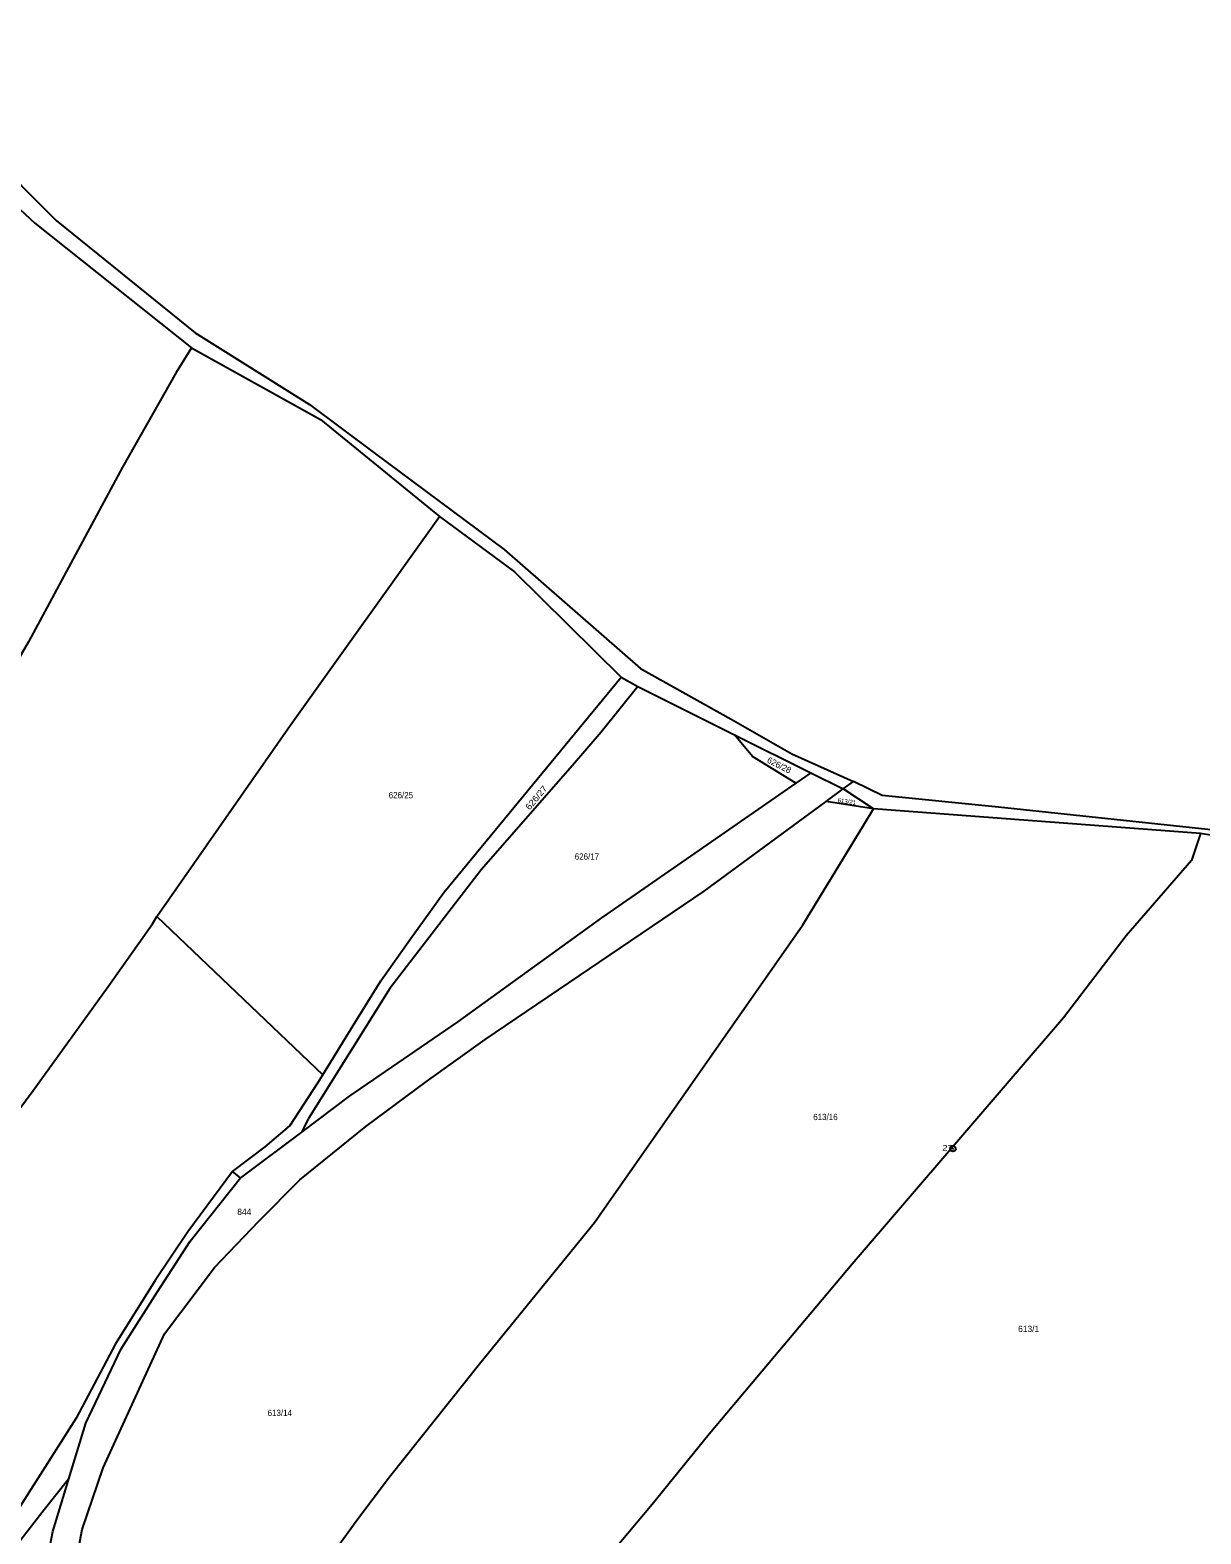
# Model space of a CAD drawing. Extents: x -687135 to -684370, y -1007309 to -1005782.
# Drawn here: x -684911.1 to -684594.1, y -1006317.9 to -1005910.8 of the extents above; entities that cross this region are included whole.
import ezdxf
from ezdxf.enums import TextEntityAlignment as Align

# ---------------------------------------------------------------- set-up
doc = ezdxf.new("R2010")
doc.units = 0
doc.header["$LTSCALE"] = 0.68
doc.layers.add('1', color=7, linetype='Continuous', lineweight=25)
doc.layers.add('8', color=7, linetype='Continuous', lineweight=25)
doc.layers.add('2', color=7, linetype='Continuous')

msp = doc.modelspace()

# ---------------------------------------------------------------- linework, layer by layer
at = {"layer": '1'}
for p, q in [((-684699.72, -1006111.87), (-684703.77, -1006114.68)), ((-684695.61, -1006119.67), (-684690.94, -1006116.24)), ((-684682.73, -1006121.59), (-684690.94, -1006116.24)), ((-684682.73, -1006121.59), (-684695.61, -1006119.67)), ((-684594.2, -1006128.33), (-684682.73, -1006121.59)), ((-684876.78, -1006150.79), (-684831.81, -1006193.68)), ((-684854.08, -1006221.54), (-684856.23, -1006219.78))]:
    msp.add_line(p, q, dxfattribs=at)
for points in [[(-684942.19, -1005910.78), (-684922.85, -1005943.49), (-684903.97, -1005962.38), (-684866.37, -1005992.78), (-684835.47, -1006012.17), (-684817.9, -1006025.25)], [(-684924.69, -1005949.22), (-684909.75, -1005963.09), (-684867.33, -1005996.85)], [(-684867.33, -1005996.85), (-684871.56, -1006003.53), (-684886.02, -1006029.12), (-684911.48, -1006076.41), (-684930.17, -1006108.46)], [(-684867.33, -1005996.85), (-684832.43, -1006016.17), (-684800.23, -1006042.43)], [(-684817.9, -1006025.25), (-684782.71, -1006051.45), (-684745.81, -1006083.61), (-684721.3, -1006097.36)], [(-684876.78, -1006150.79), (-684840.65, -1006099.06), (-684800.23, -1006042.43)], [(-684800.23, -1006042.43), (-684779.9, -1006057.47), (-684751.1, -1006085.93)], [(-684831.81, -1006193.68), (-684823.6, -1006180.27), (-684816.1, -1006168.18), (-684808.07, -1006156.86), (-684799.02, -1006144.25), (-684751.1, -1006085.93)], [(-684751.1, -1006085.93), (-684746.55, -1006088.53), (-684720.38, -1006101.58), (-684699.72, -1006111.87), (-684690.94, -1006116.24), (-684688.19, -1006114.23)], [(-684746.55, -1006088.53), (-684756.43, -1006100.82), (-684764.28, -1006109.92), (-684788.93, -1006138.13), (-684813.72, -1006170.28), (-684835.66, -1006205.48), (-684837.61, -1006209.15)], [(-684721.3, -1006097.36), (-684704.84, -1006106.77), (-684688.19, -1006114.23)], [(-684703.77, -1006114.68), (-684715.52, -1006107.49), (-684720.38, -1006101.58)], [(-684703.77, -1006114.68), (-684756.34, -1006151.1), (-684795.5, -1006179.36), (-684824.65, -1006199.4), (-684837.61, -1006209.15), (-684854.08, -1006221.54)], [(-684533.09, -1006136.3), (-684581.21, -1006128.36), (-684648.95, -1006121.18), (-684680.43, -1006118), (-684688.19, -1006114.23)], [(-684895.75, -1006421.4), (-684901.52, -1006393.47), (-684903.13, -1006370.41), (-684901.9, -1006349.06), (-684900.72, -1006336.88), (-684896.95, -1006316.71), (-684891.31, -1006300.08), (-684874.68, -1006263.75), (-684861.12, -1006245.83), (-684849.13, -1006233.21), (-684838.04, -1006222.1), (-684820.16, -1006207.64), (-684803.79, -1006195.44), (-684787.9, -1006184.05), (-684728.55, -1006143.87), (-684695.61, -1006119.67)], [(-684895.75, -1006421.4), (-684870.4, -1006380.29), (-684822.32, -1006313.86), (-684813.73, -1006302.51), (-684789.44, -1006271.88), (-684758.27, -1006233.58), (-684701.91, -1006153.06), (-684685.37, -1006125.92), (-684682.73, -1006121.59)], [(-684594.2, -1006128.33), (-684596.65, -1006135.63), (-684614.36, -1006156.02), (-684631.3, -1006178.22), (-684688.55, -1006244.87), (-684727.25, -1006290.89), (-684742.63, -1006309.98), (-684766.71, -1006338.61), (-684696.92, -1006394.18)], [(-684510.85, -1006152.6), (-684524.72, -1006143.73), (-684536.34, -1006138), (-684594.2, -1006128.33)], [(-685067.76, -1006407.52), (-685012.1, -1006340.15), (-684940.88, -1006239.13), (-684910.26, -1006197.91), (-684889.9, -1006169.75), (-684877.93, -1006152.74), (-684876.78, -1006150.79)], [(-684856.23, -1006219.78), (-684847.44, -1006213.15), (-684840.78, -1006207.47), (-684833.17, -1006195.82), (-684831.81, -1006193.68)], [(-684856.23, -1006219.78), (-684868.36, -1006236.18), (-684877.16, -1006249.29), (-684887.91, -1006266.51), (-684898.63, -1006286.6), (-684913.88, -1006310.63), (-684919.75, -1006321.58), (-684931.87, -1006339.19), (-684939.11, -1006350.34), (-684952.01, -1006369.9), (-684965.12, -1006392.2), (-684970.59, -1006402.96), (-684973.76, -1006410.29), (-684980.32, -1006434.42)], [(-684900.57, -1006302.99), (-684896, -1006287.94), (-684886.43, -1006267.86), (-684876.67, -1006252.44), (-684867.76, -1006238.68), (-684854.08, -1006221.54)], [(-684900.57, -1006302.99), (-684907.23, -1006311.42), (-684918.18, -1006325.47), (-684932.07, -1006347.35), (-684944, -1006366.68), (-684955.53, -1006384.87), (-684969.03, -1006410.25), (-684975.28, -1006437.24), (-684977.83, -1006474.8), (-684979.92, -1006493.97)], [(-684882.68, -1006473.01), (-684898.16, -1006439.92), (-684905.85, -1006415.18), (-684909.93, -1006392.37), (-684910.65, -1006373.15), (-684910.41, -1006349.38), (-684908.73, -1006337.13), (-684904.89, -1006317.24), (-684900.57, -1006302.99)]]:
    msp.add_lwpolyline(points, dxfattribs=at)
at = {"layer": '8'}
for radius in [0.75, 0.03]:
    msp.add_circle((-684661.25, -1006213.6498), radius, dxfattribs=at)

# ---------------------------------------------------------------- texts
at = {"layer": '2'}
for s, height, rotation, p in [('626/28', 1.7, 333, (-684711.765, -1006108.977)), ('613/21', 1.19, 352, (-684692.532, -1006119.859))]:
    msp.add_text(s, height=height, rotation=rotation, dxfattribs=at).set_placement(p)
at = {"layer": '2', "width": 1.1}
msp.add_text('626/27', height=1.7, rotation=50, dxfattribs=at).set_placement((-684775.828, -1006122.086))
at = {"layer": '2', "width": 0.95}
for s, p in [('626/25', (-684813.99, -1006118.77)), ('626/17', (-684763.63, -1006135.38)), ('613/16', (-684699.07, -1006205.89)), ('613/14', (-684846.77, -1006286.01))]:
    msp.add_text(s, height=1.7, dxfattribs=at).set_placement(p)
at = {"layer": '2'}
for s, p in [('844', (-684854.98, -1006231.58)), ('613/1', (-684643.6, -1006263.26))]:
    msp.add_text(s, height=1.7, dxfattribs=at).set_placement(p)
at = {"layer": '8', "width": 1.3}
msp.add_text('27', height=1.5, dxfattribs=at).set_placement((-684661.249, -1006214.15), align=Align.RIGHT)

doc.saveas('drawing.dxf')
